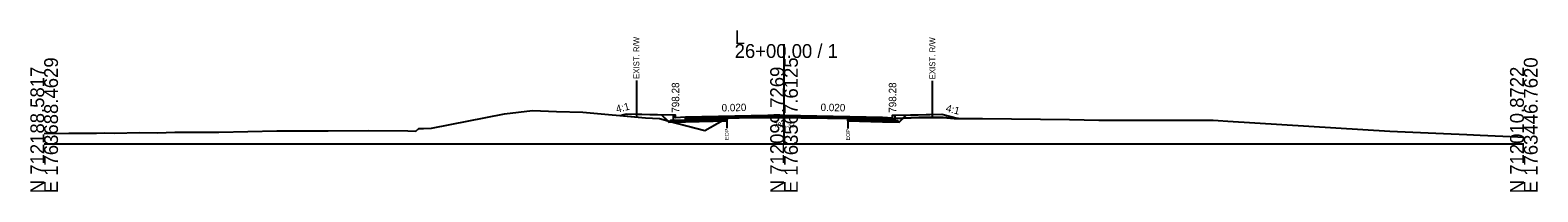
# Model space of a CAD drawing. Extents: x -26 to 5303, y -10 to 9578.
# Drawn here: x 997.2 to 1302.8, y 5990.3 to 6023 of the extents above; entities that cross this region are included whole.
import ezdxf

# ---------------------------------------------------------------- set-up
doc = ezdxf.new("R2010")
doc.units = 0
for name, color, linetype in [('Default', 7, 'Continuous'), ('Exist CMT Pavement', 7, 'Continuous'), ('Exist Cross Section Cell', 7, 'Continuous'), ('Exist XS Ground Line', 7, 'Continuous'), ('Old_Level_10', 7, 'Continuous'), ('Old_Level_3', 7, 'Continuous'), ('Prop CMT Conc Surface', 7, 'Continuous'), ('Prop CMT Concrete Structures', 7, 'Continuous'), ('Prop CMT Pvmt Course 1', 7, 'Continuous'), ('Prop CMT Pvmt Course 1 CG', 7, 'Continuous'), ('Prop CMT Pvmt Course 2', 7, 'Continuous'), ('Prop CMT Pvmt Course 3', 7, 'Continuous'), ('Prop CMT Pvmt Surface', 7, 'Continuous'), ('Prop CMT Slope Grass', 7, 'Continuous'), ('Prop CMT Subgrade Earthwork', 7, 'Continuous'), ('Prop XS Earthwork Shape', 7, 'Continuous'), ('Prop XS Hydro Elevations', 7, 'Continuous'), ('Prop XS SE Text', 7, 'Continuous'), ('Prop XS Side Slope Text', 7, 'Continuous'), ('Prop XS Wedging', 7, 'Continuous')]:
    doc.layers.add(name, color=color, linetype=linetype)

msp = doc.modelspace()

# ---------------------------------------------------------------- linework, layer by layer
at = {"layer": 'Exist CMT Pavement'}
msp.add_lwpolyline([(1138.41, 6005.2), (1139.28, 6005.25), (1140.09, 6005.26), (1142.38, 6005.31), (1143.21, 6005.31), (1145.49, 6005.33), (1146.31, 6005.33), (1147.43, 6005.33), (1148.1, 6005.32), (1148.59, 6005.32), (1149.45, 6005.32), (1150, 6005.32), (1150.58, 6005.32), (1151.69, 6005.32), (1153.46, 6005.29), (1154.79, 6005.28), (1155.25, 6005.27), (1155.87, 6005.26), (1157.9, 6005.24), (1160.09, 6005.21), (1160.61, 6005.2), (1161.28, 6005.19), (1162.55, 6005.16), (1162.96, 6005.14)], dxfattribs=at)
at = {"layer": 'Exist Cross Section Cell'}
for p, q in [((1150, 6000), (1150, 6020.17)), ((1000, 6000), (1150, 6000)), ((1150, 6000), (1300, 6000))]:
    msp.add_line(p, q, dxfattribs=at)
at = {"layer": 'Exist XS Ground Line'}
msp.add_lwpolyline([(1000, 6002.09), (1005, 6002.14), (1010.58, 6002.16), (1012.15, 6002.21), (1014.29, 6002.19), (1019.31, 6002.26), (1022.99, 6002.23), (1026.46, 6002.33), (1031.18, 6002.39), (1035.4, 6002.38), (1047.14, 6002.65), (1047.81, 6002.66), (1048.12, 6002.66), (1057.61, 6002.66), (1065.78, 6002.69), (1073.7, 6002.65), (1075.37, 6002.59), (1075.93, 6003.09), (1076.93, 6003.13), (1078.5, 6003.14), (1093.33, 6006.08), (1099.02, 6006.72), (1103.9, 6006.51), (1109.18, 6006.38), (1121.92, 6005.26), (1124.78, 6005.11), (1126.62, 6004.58), (1133.92, 6002.69), (1137.69, 6004.8), (1138.41, 6005.22), (1138.74, 6005.22), (1139.28, 6005.25), (1140.94, 6005.29), (1142.38, 6005.31), (1142.73, 6005.31), (1143.21, 6005.31), (1144.52, 6005.32), (1145.49, 6005.33), (1146.31, 6005.33), (1147.43, 6005.33), (1148.1, 6005.32), (1148.59, 6005.32), (1149.45, 6005.32), (1150, 6005.32), (1150.58, 6005.32), (1151.69, 6005.32), (1153.46, 6005.29), (1154.79, 6005.28), (1155.25, 6005.27), (1155.87, 6005.26), (1157.9, 6005.24), (1158.83, 6005.22), (1160.09, 6005.21), (1160.61, 6005.2), (1161.28, 6005.19), (1162.55, 6005.16), (1162.96, 6005.14), (1163.44, 6005.13), (1164.67, 6005.16), (1166.34, 6004.77), (1169.84, 6005.1), (1171.49, 6005.09), (1172.7, 6005.11), (1177.31, 6005.31), (1182.27, 6005.36), (1184.47, 6005.13), (1184.98, 6005.13), (1188.08, 6005.12), (1190.26, 6005.11), (1207.85, 6004.9), (1213.8, 6004.8), (1224.88, 6004.76), (1228.19, 6004.76), (1228.89, 6004.76), (1237.03, 6004.77), (1238.03, 6004.74), (1239.99, 6004.61), (1272.82, 6002.58), (1283.68, 6002.11), (1288.42, 6001.88), (1291.15, 6001.76), (1298.81, 6001.39), (1300, 6001.34)], dxfattribs=at)
at = {"layer": 'Old_Level_10'}
for p, q in [((1120.07, 6012.82), (1120.07, 6005.42)), ((1180.07, 6012.74), (1180.07, 6005.34)), ((1138.41, 6005.22), (1138.41, 6003.17)), ((1162.96, 6005.14), (1162.96, 6003.09))]:
    msp.add_line(p, q, dxfattribs=at)
at = {"layer": 'Prop CMT Conc Surface'}
for points in [[(1128, 6005.28), (1128, 6005.78), (1127.5, 6005.78)], [(1130, 6005.4), (1128, 6005.28)], [(1170, 6005.4), (1172, 6005.28)], [(1172, 6005.28), (1172, 6005.78), (1172.5, 6005.78)]]:
    msp.add_lwpolyline(points, dxfattribs=at)
at = {"layer": 'Prop CMT Concrete Structures'}
for points in [[(1130, 6005.4), (1128, 6005.28), (1128, 6005.78), (1127.5, 6005.78)], [(1127.5, 6005.78), (1127.5, 6004.76), (1130, 6004.81)], [(1130, 6004.81), (1130, 6005.4)], [(1170, 6005.4), (1172, 6005.28), (1172, 6005.78), (1172.5, 6005.78)], [(1172.5, 6005.78), (1172.5, 6004.76), (1170, 6004.81)], [(1170, 6004.81), (1170, 6005.4)]]:
    msp.add_lwpolyline(points, dxfattribs=at)
at = {"layer": 'Prop CMT Pvmt Course 1'}
for points in [[(1150, 6005.8), (1130, 6005.4)], [(1130, 6005.4), (1130, 6005.15)], [(1130, 6005.15), (1138.41, 6005.32)], [(1138.41, 6005.32), (1150, 6005.55)], [(1138.41, 6005.32), (1138.41, 6005.32)], [(1150, 6005.55), (1150, 6005.8)], [(1150, 6005.8), (1170, 6005.4)], [(1150, 6005.55), (1150, 6005.55), (1150, 6005.55)], [(1162.96, 6005.29), (1150, 6005.55)], [(1170, 6005.15), (1162.96, 6005.29)], [(1162.96, 6005.29), (1162.96, 6005.29)], [(1170, 6005.4), (1170, 6005.15)]]:
    msp.add_lwpolyline(points, dxfattribs=at)
at = {"layer": 'Prop CMT Pvmt Course 1 CG'}
for points in [[(1130, 6004.81), (1127, 6004.75), (1126.66, 6004.41)], [(1126.66, 6004.41), (1130, 6004.48)], [(1130, 6004.48), (1130, 6004.81)], [(1170, 6004.81), (1173, 6004.75), (1173.34, 6004.41)], [(1170, 6004.48), (1170, 6004.81)], [(1173.34, 6004.41), (1170, 6004.48)]]:
    msp.add_lwpolyline(points, dxfattribs=at)
at = {"layer": 'Prop CMT Pvmt Course 2'}
for points in [[(1138.41, 6005.32), (1130, 6005.15)], [(1130, 6005.15), (1130, 6004.81)], [(1130, 6004.81), (1138.41, 6004.98)], [(1138.41, 6004.98), (1138.41, 6005.32)], [(1162.96, 6004.95), (1162.96, 6005.29)], [(1162.96, 6005.29), (1170, 6005.15)], [(1170, 6004.81), (1162.96, 6004.95)], [(1170, 6005.15), (1170, 6004.81)]]:
    msp.add_lwpolyline(points, dxfattribs=at)
at = {"layer": 'Prop CMT Pvmt Course 3'}
for points in [[(1138.41, 6004.98), (1130, 6004.81)], [(1130, 6004.81), (1130, 6004.48)], [(1130, 6004.48), (1138.41, 6004.65)], [(1138.41, 6004.65), (1138.41, 6004.98)], [(1162.96, 6004.95), (1170, 6004.81)], [(1162.96, 6004.62), (1162.96, 6004.95)], [(1170, 6004.48), (1162.96, 6004.62)], [(1170, 6004.81), (1170, 6004.48)]]:
    msp.add_lwpolyline(points, dxfattribs=at)
at = {"layer": 'Prop CMT Pvmt Surface'}
for points in [[(1150, 6005.8), (1130, 6005.4)], [(1150, 6005.8), (1170, 6005.4)]]:
    msp.add_lwpolyline(points, dxfattribs=at)
at = {"layer": 'Prop CMT Slope Grass'}
for points in [[(1127.5, 6005.78), (1118, 6005.97), (1116.92, 6005.7)], [(1172.5, 6005.78), (1182, 6005.97), (1185.36, 6005.13)]]:
    msp.add_lwpolyline(points, dxfattribs=at)
at = {"layer": 'Prop CMT Subgrade Earthwork'}
for p, q in [((1138.41, 6005.2), (1138.41, 6004.65)), ((1162.96, 6005.14), (1162.96, 6004.62))]:
    msp.add_line(p, q, dxfattribs=at)
for points in [[(1130, 6004.48), (1126.66, 6004.41), (1125.25, 6005.82)], [(1138.41, 6004.65), (1130, 6004.48)], [(1162.96, 6004.62), (1170, 6004.48)], [(1170, 6004.48), (1173.34, 6004.41), (1174.75, 6005.82)]]:
    msp.add_lwpolyline(points, dxfattribs=at)
at = {"layer": 'Prop XS Earthwork Shape'}
for points in [[(1118, 6005.97), (1116.92, 6005.7), (1121.92, 6005.26), (1124.78, 6005.11), (1126.45, 6004.63), (1125.25, 6005.82)], [(1127.21, 6004.42), (1126.66, 6004.41), (1126.45, 6004.63), (1126.62, 6004.58)], [(1137.39, 6004.63), (1130, 6004.48), (1127.21, 6004.42), (1133.92, 6002.69)], [(1137.39, 6004.63), (1137.69, 6004.8), (1138.41, 6005.22), (1138.74, 6005.22), (1138.41, 6005.2), (1138.41, 6004.65)], [(1138.41, 6004.65), (1137.39, 6004.63), (1137.69, 6004.8), (1138.41, 6005.22), (1138.74, 6005.22), (1138.41, 6005.2)], [(1173.34, 6004.41), (1174.1, 6005.17), (1172.7, 6005.11), (1171.49, 6005.09), (1169.84, 6005.1), (1166.34, 6004.77), (1164.67, 6005.16), (1163.44, 6005.13), (1162.96, 6005.14), (1162.96, 6004.62), (1170, 6004.48)], [(1182, 6005.97), (1185.36, 6005.13), (1184.98, 6005.13), (1184.47, 6005.13), (1182.27, 6005.36), (1177.31, 6005.31), (1174.1, 6005.17), (1174.75, 6005.82)]]:
    msp.add_lwpolyline(points, close=True, dxfattribs=at)
at = {"layer": 'Prop XS Wedging'}
for points in [[(1138.41, 6005.22), (1138.41, 6005.32), (1138.74, 6005.32), (1139.28, 6005.33), (1140.09, 6005.35), (1142.38, 6005.39), (1143.21, 6005.41), (1145.49, 6005.46), (1146.31, 6005.47), (1147.43, 6005.5), (1148.1, 6005.51), (1148.59, 6005.52), (1149.45, 6005.54), (1150, 6005.55), (1150.58, 6005.54), (1151.69, 6005.51), (1153.46, 6005.48), (1154.79, 6005.45), (1155.25, 6005.44), (1155.87, 6005.43), (1157.9, 6005.39), (1160.09, 6005.35), (1160.61, 6005.33), (1161.28, 6005.32), (1162.55, 6005.3), (1162.96, 6005.29), (1162.96, 6005.14), (1162.55, 6005.16), (1161.28, 6005.19), (1160.61, 6005.2), (1160.09, 6005.21), (1157.9, 6005.24), (1155.87, 6005.26), (1155.25, 6005.27), (1154.79, 6005.28), (1153.46, 6005.29), (1151.69, 6005.32), (1150.58, 6005.32), (1150, 6005.32), (1149.45, 6005.32), (1148.59, 6005.32), (1148.1, 6005.32), (1147.43, 6005.33), (1146.31, 6005.33), (1145.49, 6005.33), (1143.21, 6005.31), (1142.38, 6005.31), (1140.09, 6005.26), (1139.28, 6005.25), (1138.74, 6005.22)], [(1148.97, 6005.32), (1149.18, 6005.53), (1149.45, 6005.54), (1150, 6005.55), (1150.58, 6005.54), (1150.95, 6005.53), (1151.16, 6005.32), (1150.58, 6005.32), (1150, 6005.32), (1149.45, 6005.32)]]:
    msp.add_lwpolyline(points, close=True, dxfattribs=at)

# ---------------------------------------------------------------- texts
at = {"layer": 'Default'}
msp.add_text('-', height=0.0001, dxfattribs=at).set_placement((1000, 6000))
at = {"layer": 'Exist Cross Section Cell'}
for s, p in [('L', (1140, 6020.17)), ('26+00.00 / 1', (1140, 6017.37))]:
    msp.add_text(s, height=2.8, dxfattribs=at).set_placement(p)
for s, p in [('E 1763688.4629', (1002.8, 5990)), ('E 1763567.6125', (1152.8, 5990)), ('E 1763446.7620', (1302.8, 5990)), ('N 712188.5817', (1000, 5990)), ('N 712099.7269', (1150, 5990)), ('N 712010.8722', (1300, 5990))]:
    msp.add_text(s, height=2.8, rotation=90, dxfattribs=at).set_placement(p)
at = {"layer": 'Old_Level_10'}
for s, height, p in [('EXIST. R/W', 1.181, (1120.66, 6013.12)), ('EXIST. R/W', 1.181, (1180.66, 6013.04)), ('EOP', 0.787, (1138.8, 6000.77)), ('EOP', 0.787, (1163.36, 6000.69))]:
    msp.add_text(s, height=height, rotation=90, dxfattribs=at).set_placement(p)
at = {"layer": 'Old_Level_3'}
msp.add_text('798.32', height=1, dxfattribs=at).set_placement((1147.96, 6003.32))
at = {"layer": 'Prop XS Hydro Elevations'}
for p in [(1128.75, 6006.28), (1172.75, 6006.28)]:
    msp.add_text('798.28', height=1.5, rotation=90, dxfattribs=at).set_placement(p)
at = {"layer": 'Prop XS SE Text'}
for rotation, p in [(1.1458, (1137.36, 6006.54)), (358.8542, (1157.4, 6006.65))]:
    msp.add_text('0.020', height=1.5, rotation=rotation, dxfattribs=at).set_placement(p)
at = {"layer": 'Prop XS Side Slope Text'}
for rotation, p in [(14.0362, (1116.12, 6006.27)), (345.9638, (1182.71, 6006.56))]:
    msp.add_text('4:1', height=1.5, rotation=rotation, dxfattribs=at).set_placement(p)

doc.saveas('drawing.dxf')
